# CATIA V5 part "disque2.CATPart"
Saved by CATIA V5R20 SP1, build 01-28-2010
Part number: disque1.1
Bounding box of the stored display mesh (mm): x 42.5 to 117.5, y 0 to 10, z 62.5 to 137.5
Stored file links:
  E:\EDELI\gcausse\Edeli_2012_184_gcausse\disque2.CATPart
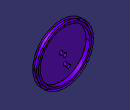
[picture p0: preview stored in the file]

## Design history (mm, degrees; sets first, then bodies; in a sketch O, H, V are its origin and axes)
Body1 (main body)
  DatumSurface1
  Sketch1 on face of DatumSurface1, origin (0, 5, 0), H (1, 0, 0), V (0, 0, 1)
    circle A1 centre (80, 100) radius 32.5
    circle A2 centre (80, 100) radius 2.5
    radius A1 = 32.5
    radius A2 = 2.5
  Pad1: profile Sketch1, direction (0, -1, 0), length 5
Body2
  Sketch2 on start face of Pad1, origin (0, 5, 0), H (-1, 0, 0), V (0, 0, 1)
    circle A1 centre (-80, 100) radius 35
    circle A2 centre (-80, 100) radius 32.5
    radius A2 = 32.5
    radius A1 = 35
  Pad2: profile Sketch2, direction (0, -1, 0), length 5
  Sketch3 on start face of Pad1, origin (0, 5, 0), H (-1, 0, 0), V (0, 0, 1)
Body3
  Sketch4 on start face of Pad1, origin (0, 5, 0), H (-1, 0, 0), V (0, 0, 1)
    circle A1 centre (-80, 100) radius 37.5
    circle A2 centre (-80, 100) radius 35
    radius A2 = 35
    radius A1 = 37.5
  Pad3: profile Sketch4, direction (0, -1, 0), length 5
  Sketch5 on start face of Pad1, origin (0, 5, 0), H (-1, 0, 0), V (0, 0, 1)
    circle A1 centre (-80, 90) radius 2.5
    radius A1 = 2.5
  Pad4: profile Sketch5, direction (0, 1, 0), length 5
